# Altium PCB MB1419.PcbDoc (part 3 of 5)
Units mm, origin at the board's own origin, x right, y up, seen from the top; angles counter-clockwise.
Board outline 31 x 41 mm, 8 copper layers (Top Layer, Signal Layer 1, Signal Layer 2, Signal Layer 3, Signal Layer 4, Signal Layer 5, Signal Layer 6, Bottom Layer), stack 1.536 mm thick; 212 components, 125 nets, 637 pads, 2405 vias.
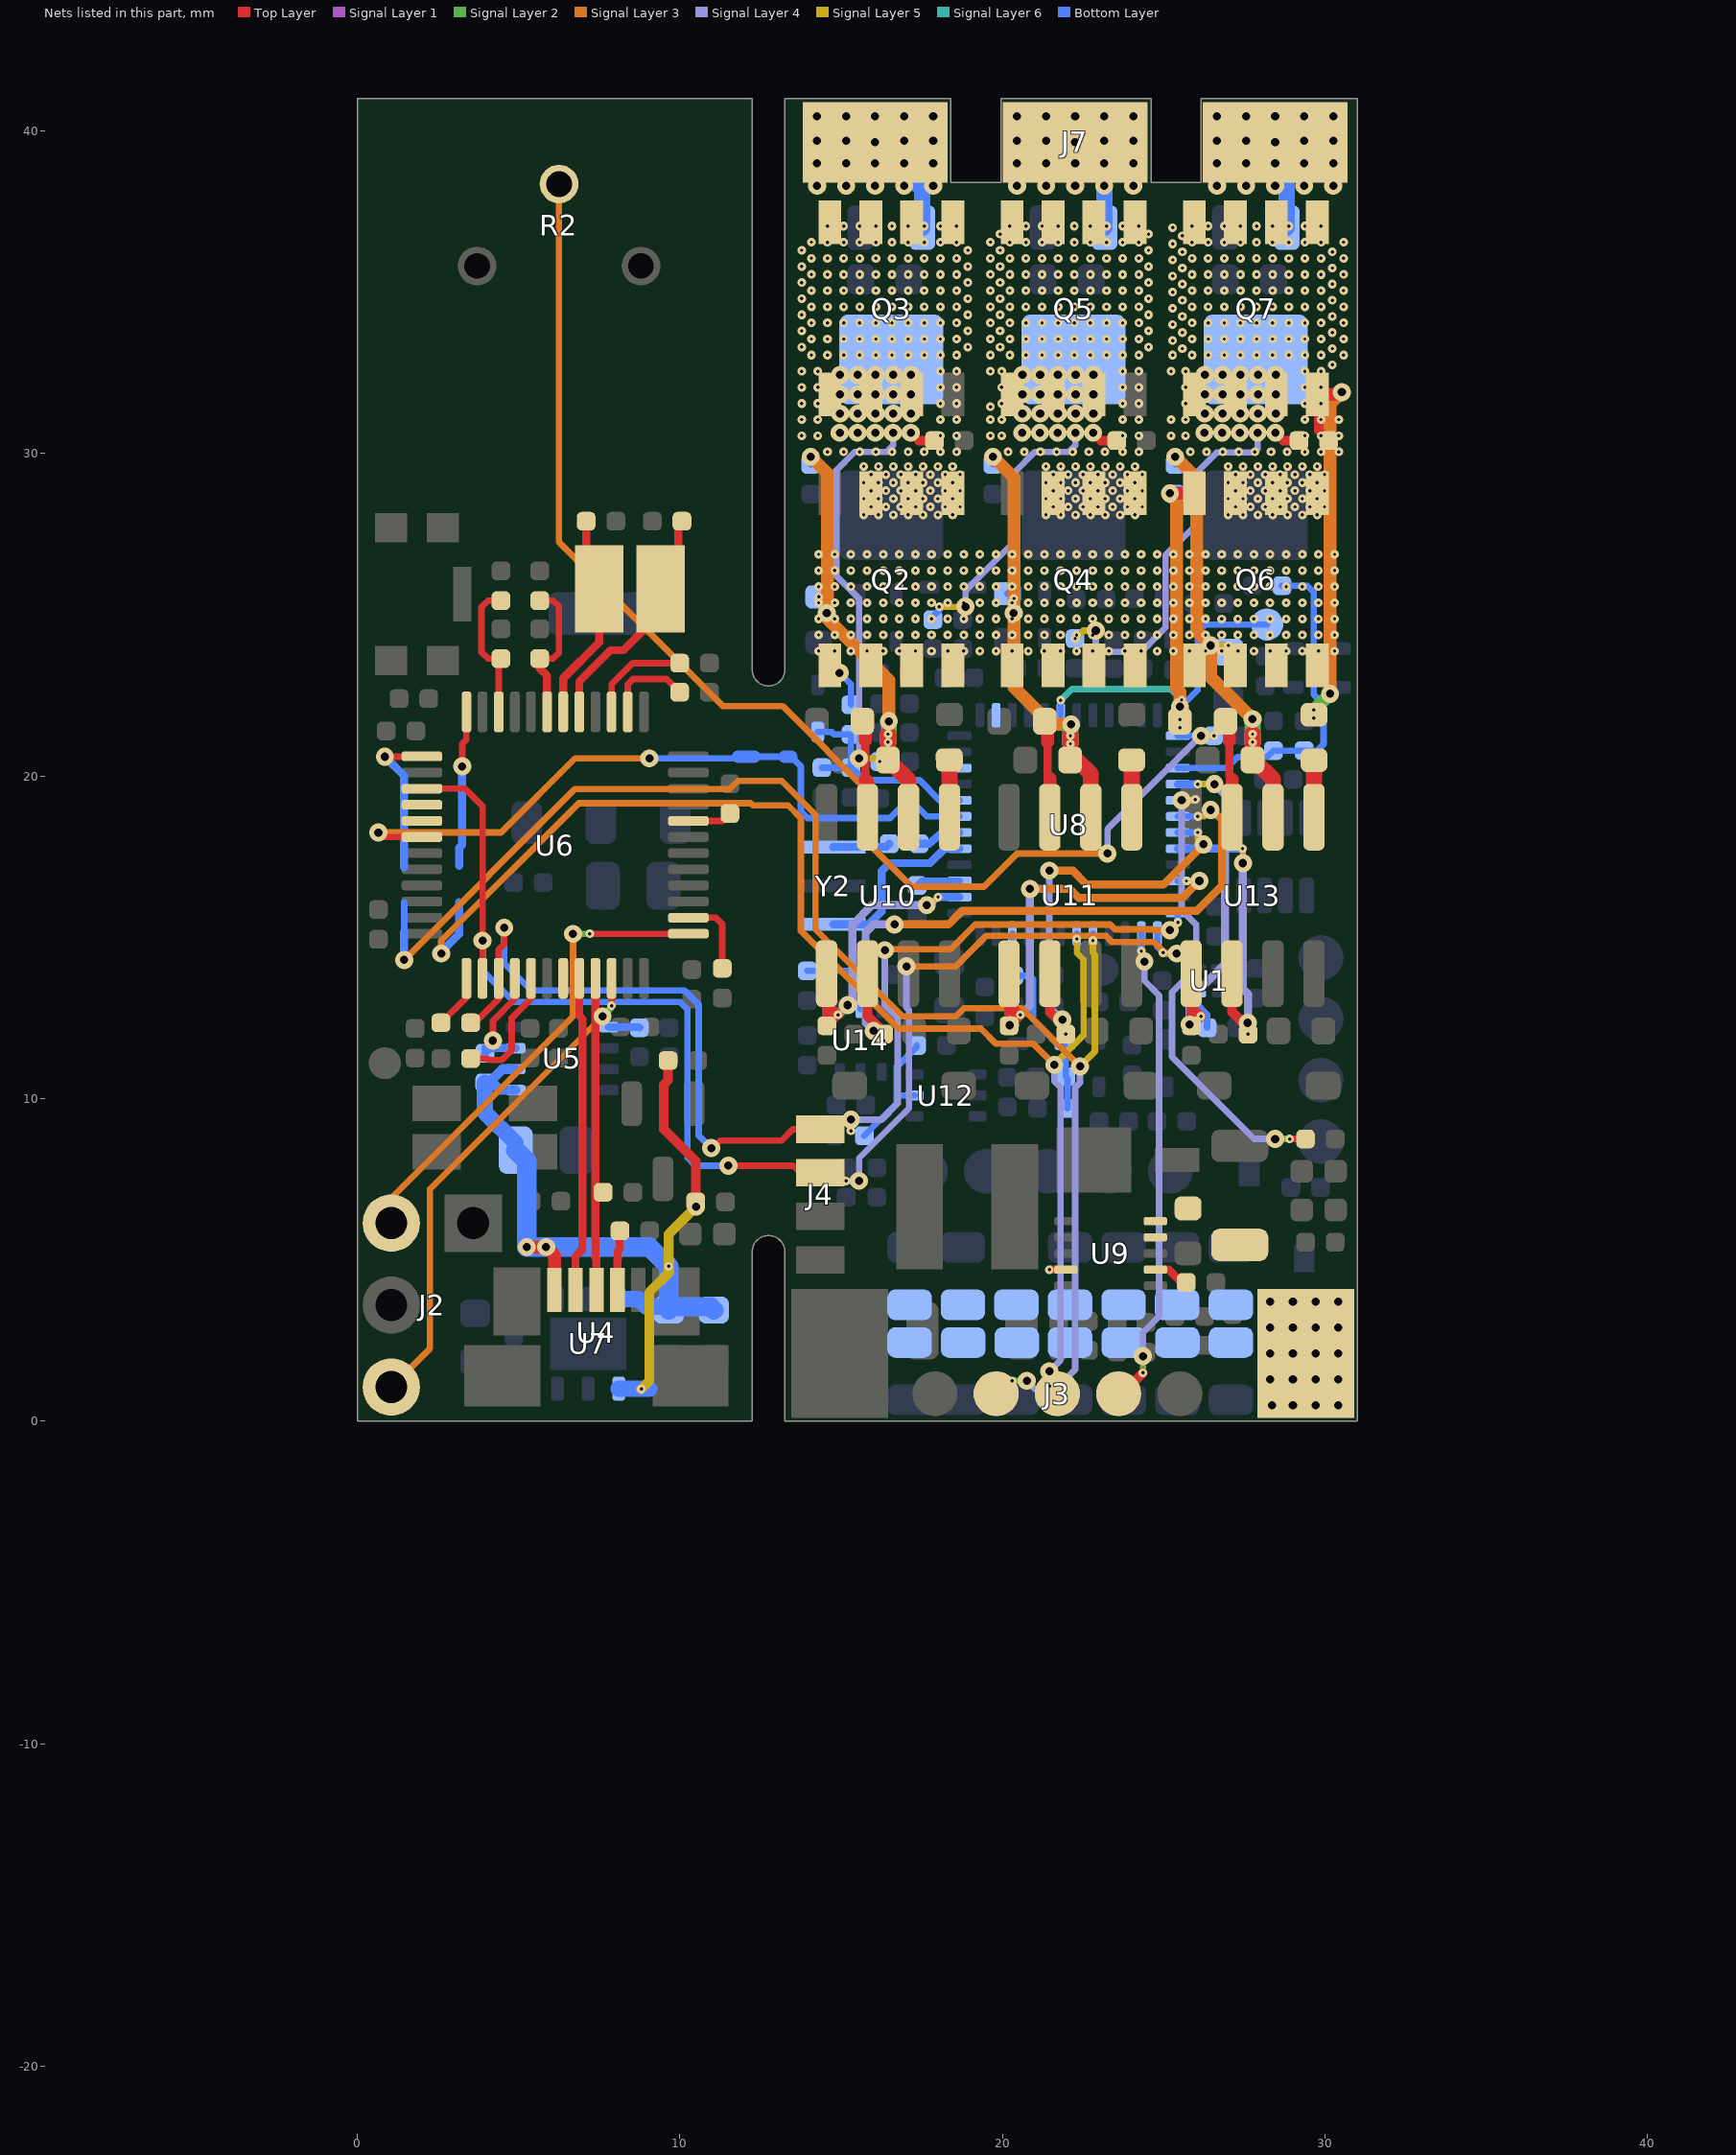
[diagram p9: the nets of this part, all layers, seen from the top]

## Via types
v1: diameter 0.27, hole 0.1, Top Layer to Signal Layer 1, 715 vias
v2: diameter 0.27, hole 0.1, Signal Layer 6 to Bottom Layer, 503 vias
v3: diameter 0.27, hole 0.1, Signal Layer 1 to Signal Layer 2, 497 vias
v4: diameter 0.27, hole 0.1, Signal Layer 5 to Signal Layer 6, 309 vias
v5: diameter 0.559, hole 0.254, Top Layer to Bottom Layer, 214 vias
v6: diameter 0.559, hole 0.254, Signal Layer 2 to Signal Layer 5, 155 vias
v7: diameter 0.254, hole 0.254, Top Layer to Bottom Layer, 12 vias

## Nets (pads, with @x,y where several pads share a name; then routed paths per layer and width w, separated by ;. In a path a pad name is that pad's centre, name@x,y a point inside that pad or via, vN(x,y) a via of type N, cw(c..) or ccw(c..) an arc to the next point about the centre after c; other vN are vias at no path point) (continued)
NetQ6_4: Q6.4 R47.2 R48.1 | length 8.6
  Top Layer w0.2: v3(25.5,21.5) R47.2@25.5,21.7 R47.2@25.545,21.7
  Top Layer w0.4: v5(25.184,28.765) Q6.4@25.945,28.765
  Signal Layer 2 w0.4: v3(25.5,21.5) v3(25.5,21.75) v6(25.5,22.15)
  Signal Layer 3 w0.4: v5(25.184,28.765) 25.4,28.549 25.4,22.7 25.5,22.6 v6(25.5,22.15)
  Bottom Layer w0.2: v5(25.184,28.765) 25.325,28.765 R48.1@25.35,28.74
  other v1: 25.5,21.5 25.5,21.75
NetQ7_4: Q7.4 R50.2 R52.1 | length 13.1
  Top Layer w0.2: v3(29.65,21.8) 29.655,21.805 R50.2@29.655,21.9 R50.2@29.65,21.905 ; R52.1@30,30.51 30,30.5 30.1,30.4 R52.1@30.11,30.4
  Top Layer w0.3: Q7.4@29.755,31.835 29.8,31.79 29.8,30.71 30,30.51 R52.1@30.11,30.4
  Top Layer w0.4: Q7.4@29.755,31.835 30.385,31.835 30.45,31.9 v5(30.516,31.9)
  Signal Layer 2 w0.4: v3(29.65,21.8) v3(29.65,22.05) v6(30.15,22.55)
  Signal Layer 3 w0.4: v6@30.15,22.5 v6(30.15,22.55) 30.15,31.534 v5(30.516,31.9)
  other v1: 29.65,21.8 29.65,22.05
NetR7_2: R7.2 U4.4 | length 1.9
  Top Layer w0.25: U4.4@8.06,4.074 8.06,5.011 8.07,5.021 8.07,5.288 8.14,5.358 R7.2@8.14,5.9
NetR13_1: R13.1 U6.44 | length 1.4
  Top Layer w0.2: U6.44@10.26,18.61 11.32,18.61 R13.1@11.55,18.84
NetR14_1: R14.1 U5.5 | length 1
  Bottom Layer w0.25: U5.5@7.795,12.215 8.725,12.215 R14.1@8.74,12.2
NetR16_1: R16.1 U6.2 | length 2.7
  Top Layer w0.2: U6.2@8.38,21.99 8.38,22.847 8.54,23.007 9.583,23.007 R16.1@9.99,22.6
NetR17_1: R17.1 U6.3 | length 3.2
  Top Layer w0.2: U6.3@7.88,21.99 7.88,22.847 8.533,23.5 R17.1@9.99,23.5
NetR18_2: R18.2 U6.29 | length 3.9
  Top Layer w0.2: R18.2@3.51,11.24 4.027,11.24 4.067,11.2 4.48,11.2 4.78,11.5 4.78,12.498 5.38,13.098 U6.29@5.38,13.73
NetR19_1: R19.1 R22.1 U6.10 | length 4.4
  Top Layer w0.2: U6.10@4.38,21.99 4.38,23.57 R22.1@4.45,23.64 4.048,23.64 3.848,23.84 3.848,25.24 4.048,25.44 R19.1@4.45,25.44
NetR23_2: R23.2 U6.12 | length 4.9
  Top Layer w0.2: v5(3.25,20.3) 3.25,21.003 3.38,21.133 U6.12@3.38,21.99
  Bottom Layer w0.25: R23.2@3.15,17.22 3.15,17.767 3.25,17.867 v5(3.25,20.3)
NetR24_2: R24.2 U6.13 | length 4.8
  Top Layer w0.2: v5(0.85,20.6) 1.99,20.6 U6.13@2,20.61
  Bottom Layer w0.25: v5(0.85,20.6) 1.45,20 R24.2@1.45,17.22 1.45,17.17
NetR26_1: R26.1 U8.3 | length 1.4
  Bottom Layer w0.2: R26.1@17.35,16.61 17.49,16.75 U8.3@18.665,16.75
NetR27_1: R27.1 Y2.3 | length 1.8
  Bottom Layer w0.25: Y2.3@14.75,17.8 16.196,17.805 16.395,17.805 R27.1@16.49,17.9
NetR27_2: R27.2 U8.6 | length 1.4
  Bottom Layer w0.25: R27.2@17.41,17.9 17.721,17.9 18.121,18.25 U8.6@18.665,18.25
NetR32_1: R32.1 U9.7 | length 1.1
  Top Layer w0.25: U9.7@24.735,4.7 25.149,4.7 25.549,4.3 R32.1@25.69,4.3
NetR34_1: R34.1 U10.7 | length 3.1
  Top Layer w0.2: R34.1@15.655,21.7 R34.1@15.695,21.7
  Top Layer w0.25: 15.75,19.9 15.75,21.1
  Top Layer w0.4: R34.1@15.655,21.7 15.75,21.605 15.75,21.1 ; 15.75,19.9 15.815,19.835 U10.7@15.815,18.725
NetR38_1: R38.1 U10.5 | length 1.8
  Top Layer w0.5: R38.1@18.35,20.495 18.355,20.49 U10.5@18.355,18.725
NetR40_1: R40.1 U11.7 | length 3
  Top Layer w0.25: 21.4,21.05 21.4,19.984 21.465,19.919
  Top Layer w0.4: R40.1@21.305,21.7 21.4,21.605 21.4,21.05 ; U11.7@21.465,18.725 21.465,19.919
NetR42_1: R42.1 R46.1 U12.2 | length 4
  Bottom Layer w0.2: R42.1@15.71,8.85 16.715,9.855 16.715,10.1 ; U12.2@17.275,10.1 16.715,10.1 ; R46.1@17.34,11.65 17.34,11.604 16.715,10.979 16.715,10.1
NetR43_1: R43.1 U11.5 | length 1.8
  Top Layer w0.5: R43.1@24,20.495 24.005,20.49 U11.5@24.005,18.725
NetR47_1: R47.1 U13.7 | length 3.1
  Top Layer w0.25: 27.03,21.081 27.03,19.985 27.115,19.9
  Top Layer w0.4: R47.1@26.91,21.7 26.955,21.7 27.03,21.625 27.03,21.081 ; U13.7@27.115,18.725 27.115,19.9
NetR49_1: R49.1 R53.1 U14.2 | length 3
  Bottom Layer w0.2: R49.1@13.95,13.96 15.63,13.96 R53.1@15.74,13.85 15.632,13.742 15.632,13.314 15.6,13.282 U14.2@15.6,12.775
NetR50_1: R50.1 U13.5 | length 1.8
  Top Layer w0.5: U13.5@29.655,18.725 R50.1@29.655,20.49
NetU8_5: U8.5 Y2.1 | length 5.6
  Bottom Layer w0.25: Y2.1@14.75,15.4 15.85,15.4 16.25,15.8 16.25,17.05 16.5,17.3 17.75,17.3 18.2,17.75 U8.5@18.665,17.75
OP1_OUT: U8.10 | length 0.9
  Bottom Layer w0.2: 18.005,20.65 18.005,20.54 18.295,20.25 U8.10@18.665,20.25
OP2_OUT: U8.14
OP3_OUT: TP3.1 U8.18 | length 9.2
  Signal Layer 6 w0.2: v2(21.8,22.35) 22.15,22.7 25.21,22.7 v2(25.55,22.36)
  Bottom Layer w0.2: U8.18@21.8,21.885 v2(21.8,22.35) ; v2(25.55,22.36) 25.56,22.37 25.75,22.37 26.05,22.67 26.05,24.45 26.3,24.7 TP3.1@28.2,24.7
OSC_IN: C11.2 U6.5 Y1.1 | length 7.5
  Top Layer w0.25: U6.5@6.88,21.99 6.88,22.93 7.85,23.9 8.25,23.9 8.8,24.45 8.8,25.3 9.3,25.8 Y1.1@9.4,25.8 9.4,25.9 9.95,26.45 9.95,27.79 C11.2@10.06,27.9
OSC_OUT: C10.2 U6.6 Y1.2 | length 6.6
  Top Layer w0.25: U6.6@6.38,21.99 6.38,23.03 7.5,24.15 Y1.2@7.5,25.8 7.34,25.8 7.09,26.05 C10.2@7.09,27.9
OUT1: C43.2 J7.3 Q2.1 Q2.2 Q2.3 Q3.5 Q3.6 Q3.7 Q3.8 R35.2 R37.1 R61.1 U10.6 | length 20.5
  Top Layer w0.5: C43.2@16.445,20.5 C43.2@16.45,20.5 ; v3(16.45,21.3) v3(16.45,21.05) C43.2@16.45,20.5 ; U10.6@17.085,18.025 U10.6@17.085,18.725 17.085,19.865 C43.2@16.45,20.5
  Signal Layer 1 w0.2: v5(14.25,39.7) 14.75,39.7 14.75,39.694 14.706,39.65 ; 14.85,39.65 J7.3@16.05,39.65
  Signal Layer 2 w0.5: v3(16.45,21.05) v3(16.45,21.3) 16.474,21.324 v6(16.474,21.7)
  Signal Layer 3 w0.2: v6(14.55,25.05) 14.55,24.9 v6@14.571,24.879 ; 14.55,25.5 14.571,25.521 14.65,25.6 14.65,26.221 14.571,26.3
  Signal Layer 3 w0.4: v5(14.05,29.9) 14.571,29.379 14.571,26.3 14.571,25.521 14.571,24.879 16.474,22.976 v6(16.474,21.7)
  Signal Layer 5 w0.2: v4(14.3,25.555) 14.445,25.41 14.445,25.155 v6(14.55,25.05)
  Bottom Layer w0.2: R35.2@14.05,29.66 v5(14.05,29.9) ; v4(14.3,25.555) 14.355,25.5 14.445,25.5 R61.1@14.45,25.495
  Bottom Layer w0.5: J7.3@16.05,39.65 16.825,38.875 17.175,38.525 17.51,38.19 R37.1@17.51,37
  other v1: 16.45,21.05 16.45,21.3 15.692,28.097 16.153,28.097 16.612,28.097 17.073,28.097 17.532,28.097 17.992,28.097 18.453,28.097 15.923,28.347 16.382,28.347 16.842,28.347 17.303,28.347 17.762,28.347 18.222,28.347 18.683,28.347 15.692,28.597 16.153,28.597 16.612,28.597 17.073,28.597 17.532,28.597 17.992,28.597 18.453,28.597 15.923,28.847 16.382,28.847 16.842,28.847 17.303,28.847 17.762,28.847 18.222,28.847 18.683,28.847 15.692,29.097 16.153,29.097 16.612,29.097 17.073,29.097 17.532,29.097 17.992,29.097 18.453,29.097 15.923,29.347 16.382,29.347 16.842,29.347 17.303,29.347 17.762,29.347 18.222,29.347 18.683,29.347 15.692,29.597 16.153,29.597 16.612,29.597 17.073,29.597 17.532,29.597 17.992,29.597 18.453,29.597 14.573,33.55 15.073,33.55 15.573,33.55 16.073,33.55 16.573,33.55 17.073,33.55 17.573,33.55 18.073,33.55 18.573,33.55 14.573,34.05 15.073,34.05 15.573,34.05 16.073,34.05 16.573,34.05 17.073,34.05 17.573,34.05 18.073,34.05 18.573,34.05 14.573,34.55 15.073,34.55 15.573,34.55 16.073,34.55 16.573,34.55 17.073,34.55 17.573,34.55 18.073,34.55 18.573,34.55 14.573,35.05 15.073,35.05 15.573,35.05 16.073,35.05 16.573,35.05 17.073,35.05 17.573,35.05 18.073,35.05 18.573,35.05 14.573,35.55 15.073,35.55 15.573,35.55 16.073,35.55 16.573,35.55 17.073,35.55 17.573,35.55 18.073,35.55 18.573,35.55 14.573,36.05 15.073,36.05 15.573,36.05 16.073,36.05 16.573,36.05 17.073,36.05 17.573,36.05 18.073,36.05 18.573,36.05 14.573,36.55 15.073,36.55 15.573,36.55 16.073,36.55 16.573,36.55 17.073,36.55 17.573,36.55 18.073,36.55 18.573,36.55 14.573,37.05 15.073,37.05 15.573,37.05 16.073,37.05 16.573,37.05 17.073,37.05 17.573,37.05 18.073,37.05 18.573,37.05
  other v2: 14.3,25.555
  other v3: 14.573,30.05 15.073,30.05 15.573,30.05 16.073,30.05 16.573,30.05 17.073,30.05 17.573,30.05 18.073,30.05 18.573,30.05 13.773,30.55 14.273,30.55 18.073,30.55 18.573,30.55 13.773,31.05 14.273,31.05 18.073,31.05 18.573,31.05 13.773,31.55 14.273,31.55 18.073,31.55 18.573,31.55 13.773,32.05 14.273,32.05 18.073,32.05 18.573,32.05 13.773,32.55 14.273,32.55 18.073,32.55 18.573,32.55 14.073,33.05 14.573,33.05 15.073,33.05 15.573,33.05 16.073,33.05 16.573,33.05 17.073,33.05 17.573,33.05 18.073,33.05 18.573,33.05 13.773,33.3 18.923,33.3 14.073,33.55 14.573,33.55 15.073,33.55 15.573,33.55 16.073,33.55 16.573,33.55 17.073,33.55 17.573,33.55 18.073,33.55 18.573,33.55 13.773,33.8 18.923,33.8 14.073,34.05 14.573,34.05 15.073,34.05 15.573,34.05 16.073,34.05 16.573,34.05 17.073,34.05 17.573,34.05 18.073,34.05 18.573,34.05 13.773,34.3 18.923,34.3 14.073,34.55 14.573,34.55 15.073,34.55 15.573,34.55 16.073,34.55 16.573,34.55 17.073,34.55 17.573,34.55 18.073,34.55 18.573,34.55 13.773,34.8 18.923,34.8 14.073,35.05 14.573,35.05 15.073,35.05 15.573,35.05 16.073,35.05 16.573,35.05 17.073,35.05 17.573,35.05 18.073,35.05 18.573,35.05 13.773,35.3 18.923,35.3 14.073,35.55 14.573,35.55 15.073,35.55 15.573,35.55 16.073,35.55 16.573,35.55 17.073,35.55 17.573,35.55 18.073,35.55 18.573,35.55 13.773,35.8 18.923,35.8 14.073,36.05 14.573,36.05 15.073,36.05 15.573,36.05 16.073,36.05 16.573,36.05 17.073,36.05 17.573,36.05 18.073,36.05 18.573,36.05 13.773,36.3 18.923,36.3 14.073,36.55 14.573,36.55 15.073,36.55 15.573,36.55 16.073,36.55 16.573,36.55 17.073,36.55 17.573,36.55 18.073,36.55 18.573,36.55 14.573,37.05 15.073,37.05 15.573,37.05 16.073,37.05 16.573,37.05 17.073,37.05 17.573,37.05 18.073,37.05 18.573,37.05
  other v5: 14.25,38.3 15.15,38.3 16.05,38.3 16.95,38.3 17.85,38.3 14.25,39 15.15,39 16.05,39 16.95,39 17.85,39 15.15,39.7 16.95,39.7 17.85,39.7 14.25,40.45 15.15,40.45 16.05,40.45 16.95,40.45 17.85,40.45
OUT2: C52.2 J7.2 Q4.1 Q4.2 Q4.3 Q5.5 Q5.6 Q5.7 Q5.8 R41.2 R44.1 R62.1 U11.6 | length 18.1
  Top Layer w0.5: C52.2@22.095,20.5 C52.2@22.1,20.5 ; v3(22.1,21.25) v3(22.1,21) C52.2@22.1,20.5 ; U11.6@22.735,18.725 22.735,20.065 22.3,20.5 C52.2@22.1,20.5
  Signal Layer 2 w0.5: v3(22.1,21) 22.1,21.3 22.1,21.576 v6(22.124,21.6)
  Signal Layer 3 w0.2: v6(20.345,25.055) 20.345,25.995 20.35,26
  Signal Layer 3 w0.4: v5(19.7,29.9) 20.35,29.25 20.35,26 20.35,22.75 21.5,21.6 v6(22.124,21.6)
  Signal Layer 5 w0.2: v6(20.345,25.055) 20.345,25.5 v4(20.35,25.505)
  Bottom Layer w0.2: R41.2@19.7,29.66 v5(19.7,29.9) ; R62.1@20.15,25.655 20.2,25.655 v4(20.35,25.505)
  Bottom Layer w0.5: J7.2@22.25,39.65 23.025,38.875 23.16,38.74 R44.1@23.16,37
  other v1: 22.1,21 22.1,21.25 21.342,28.097 21.802,28.097 22.263,28.097 22.722,28.097 23.182,28.097 23.643,28.097 24.102,28.097 21.572,28.347 22.032,28.347 22.493,28.347 22.952,28.347 23.413,28.347 23.872,28.347 24.332,28.347 21.342,28.597 21.802,28.597 22.263,28.597 22.722,28.597 23.182,28.597 23.643,28.597 24.102,28.597 21.572,28.847 22.032,28.847 22.493,28.847 22.952,28.847 23.413,28.847 23.872,28.847 24.332,28.847 21.342,29.097 21.802,29.097 22.263,29.097 22.722,29.097 23.182,29.097 23.643,29.097 24.102,29.097 21.572,29.347 22.032,29.347 22.493,29.347 22.952,29.347 23.413,29.347 23.872,29.347 24.332,29.347 21.342,29.597 21.802,29.597 22.263,29.597 22.722,29.597 23.182,29.597 23.643,29.597 24.102,29.597 20.223,33.55 20.723,33.55 21.223,33.55 21.723,33.55 22.223,33.55 22.723,33.55 23.223,33.55 23.723,33.55 24.223,33.55 20.223,34.05 20.723,34.05 21.223,34.05 21.723,34.05 22.223,34.05 22.723,34.05 23.223,34.05 23.723,34.05 24.223,34.05 20.223,34.55 20.723,34.55 21.223,34.55 21.723,34.55 22.223,34.55 22.723,34.55 23.223,34.55 23.723,34.55 24.223,34.55 20.223,35.05 20.723,35.05 21.223,35.05 21.723,35.05 22.223,35.05 22.723,35.05 23.223,35.05 23.723,35.05 24.223,35.05 20.223,35.55 20.723,35.55 21.223,35.55 21.723,35.55 22.223,35.55 22.723,35.55 23.223,35.55 23.723,35.55 24.223,35.55 19.923,35.8 24.523,35.8 19.623,36.05 20.223,36.05 20.723,36.05 21.223,36.05 21.723,36.05 22.223,36.05 22.723,36.05 23.223,36.05 23.723,36.05 24.223,36.05 19.923,36.3 24.523,36.3 19.623,36.55 20.223,36.55 20.723,36.55 21.223,36.55 21.723,36.55 22.223,36.55 22.723,36.55 23.223,36.55 23.723,36.55 24.223,36.55 19.923,36.8 24.523,36.8 20.223,37.05 20.723,37.05 21.223,37.05 21.723,37.05 22.223,37.05 22.723,37.05 23.223,37.05 23.723,37.05 24.223,37.05
  other v2: 20.35,25.505
  other v3: 20.173,30.05 20.673,30.05 21.173,30.05 21.673,30.05 22.173,30.05 22.673,30.05 23.173,30.05 23.723,30.05 24.223,30.05 19.623,30.55 19.973,30.55 23.723,30.55 24.223,30.55 19.623,31.05 19.973,31.05 23.723,31.05 24.223,31.05 19.623,31.45 19.973,31.55 23.723,31.55 24.223,31.55 19.973,32.05 23.723,32.05 24.223,32.05 19.623,32.55 19.973,32.55 23.723,32.55 24.223,32.55 19.623,33.05 20.223,33.05 20.723,33.05 21.223,33.05 21.723,33.05 22.223,33.05 22.723,33.05 23.223,33.05 23.723,33.05 24.223,33.05 19.923,33.3 24.523,33.3 19.623,33.55 20.223,33.55 20.723,33.55 21.223,33.55 21.723,33.55 22.223,33.55 22.723,33.55 23.223,33.55 23.723,33.55 24.223,33.55 19.923,33.8 24.523,33.8 19.623,34.05 20.223,34.05 20.723,34.05 21.223,34.05 21.723,34.05 22.223,34.05 22.723,34.05 23.223,34.05 23.723,34.05 24.223,34.05 19.923,34.3 24.523,34.3 19.623,34.55 20.223,34.55 20.723,34.55 21.223,34.55 21.723,34.55 22.223,34.55 22.723,34.55 23.223,34.55 23.723,34.55 24.223,34.55 19.923,34.8 24.523,34.8 19.623,35.05 20.223,35.05 20.723,35.05 21.223,35.05 21.723,35.05 22.223,35.05 22.723,35.05 23.223,35.05 23.723,35.05 24.223,35.05 19.923,35.3 24.523,35.3 19.623,35.55 20.223,35.55 20.723,35.55 21.223,35.55 21.723,35.55 22.223,35.55 22.723,35.55 23.223,35.55 23.723,35.55 24.223,35.55 19.923,35.8 24.523,35.8 19.623,36.05 20.223,36.05 20.723,36.05 21.223,36.05 21.723,36.05 22.223,36.05 22.723,36.05 23.223,36.05 23.723,36.05 24.223,36.05 19.923,36.3 24.523,36.3 19.623,36.55 20.223,36.55 20.723,36.55 21.223,36.55 21.723,36.55 22.223,36.55 22.723,36.55 23.223,36.55 23.723,36.55 24.223,36.55 19.923,36.8 24.523,36.8 20.223,37.05 20.723,37.05 21.223,37.05 21.723,37.05 22.223,37.05 22.723,37.05 23.223,37.05 23.723,37.05 24.223,37.05
  other v5: 20.45,38.3 21.35,38.3 22.25,38.3 23.15,38.3 24.05,38.3 20.45,39 21.35,39 22.25,39 23.15,39 24.05,39 20.45,39.7 21.35,39.7 23.15,39.7 24.05,39.7 20.45,40.45 21.35,40.45 22.25,40.45 23.15,40.45 24.05,40.45
OUT3: C58.2 J7.1 Q6.1 Q6.2 Q6.3 Q7.5 Q7.6 Q7.7 Q7.8 R48.2 R51.1 R63.1 U13.6 | length 16.5
  Top Layer w0.5: C58.2@27.745,20.5 C58.2@27.75,20.5 ; v3(27.75,21.3) v3(27.75,21.05) C58.2@27.75,20.5 ; U13.6@28.385,18.725 28.385,19.9 27.785,20.5 C58.2@27.75,20.5
  Signal Layer 2 w0.5: v3(27.75,21.05) v3(27.75,21.3) v6(27.75,21.766)
  Signal Layer 3 w0.4: v5(25.35,29.9) 26.021,29.229 26.021,24.479 v6(26.45,24.05) 26.45,23.066 v6(27.75,21.766)
  Signal Layer 5 w0.2: v6(26.45,24.05) v4(27,24.05)
  Bottom Layer w0.2: R48.2@25.35,29.66 v5(25.35,29.9) ; R63.1@27,23.845 v4(27,24.05) ; v5(28.45,39) J7.1@28.45,39.65
  Bottom Layer w0.5: v5(28.45,39) 28.45,38.906 28.753,38.603 28.81,38.546 R51.1@28.81,37
  other v1: 27.75,21.05 27.75,21.3 26.992,28.097 27.453,28.097 27.912,28.097 28.372,28.097 28.833,28.097 29.292,28.097 29.753,28.097 27.223,28.347 27.682,28.347 28.142,28.347 28.603,28.347 29.062,28.347 29.522,28.347 29.983,28.347 26.992,28.597 27.453,28.597 27.912,28.597 28.372,28.597 28.833,28.597 29.292,28.597 29.753,28.597 27.223,28.847 27.682,28.847 28.142,28.847 28.603,28.847 29.062,28.847 29.522,28.847 29.983,28.847 26.992,29.097 27.453,29.097 27.912,29.097 28.372,29.097 28.833,29.097 29.292,29.097 29.753,29.097 27.223,29.347 27.682,29.347 28.142,29.347 28.603,29.347 29.062,29.347 29.522,29.347 29.983,29.347 26.992,29.597 27.453,29.597 27.912,29.597 28.372,29.597 28.833,29.597 29.292,29.597 29.753,29.597 25.873,33.55 26.373,33.55 26.873,33.55 27.373,33.55 27.873,33.55 28.373,33.55 28.873,33.55 29.373,33.55 29.873,33.55 25.873,34.05 26.373,34.05 26.873,34.05 27.373,34.05 27.873,34.05 28.373,34.05 28.873,34.05 29.373,34.05 29.873,34.05 25.873,34.55 26.373,34.55 26.873,34.55 27.373,34.55 27.873,34.55 28.373,34.55 28.873,34.55 29.373,34.55 29.873,34.55 25.873,35.05 26.373,35.05 26.873,35.05 27.373,35.05 27.873,35.05 28.373,35.05 28.873,35.05 29.373,35.05 29.873,35.05 25.873,35.55 26.373,35.55 26.873,35.55 27.373,35.55 27.873,35.55 28.373,35.55 28.873,35.55 29.373,35.55 29.873,35.55 25.573,35.75 30.223,35.75 25.273,36 25.873,36.05 26.373,36.05 26.873,36.05 27.373,36.05 27.873,36.05 28.373,36.05 28.873,36.05 29.373,36.05 29.873,36.05 25.573,36.25 30.223,36.25 25.273,36.5 25.873,36.55 26.373,36.55 26.873,36.55 27.373,36.55 27.873,36.55 28.373,36.55 28.873,36.55 29.373,36.55 29.873,36.55 25.573,36.75 25.273,37 25.873,37.05 26.373,37.05 26.873,37.05 27.373,37.05 27.873,37.05 28.373,37.05 28.873,37.05 29.373,37.05 29.873,37.05
  other v2: 27,24.05
  other v3: 25.823,30.05 26.323,30.05 26.823,30.05 27.323,30.05 27.823,30.05 28.323,30.05 28.823,30.05 29.373,30.05 29.873,30.05 30.423,30.05 25.223,30.55 25.673,30.55 29.373,30.55 29.873,30.55 30.423,30.55 25.223,31.05 25.673,31.05 29.373,31.05 29.873,31.05 30.423,31.05 25.673,31.55 29.373,31.55 29.873,31.55 25.673,32.05 29.373,32.05 29.873,32.05 25.223,32.55 25.673,32.55 29.373,32.55 29.873,32.55 30.223,32.75 25.273,33.05 25.873,33.05 26.373,33.05 26.873,33.05 27.373,33.05 27.873,33.05 28.373,33.05 28.873,33.05 29.373,33.05 29.873,33.05 30.573,33.05 25.573,33.25 30.223,33.25 25.273,33.5 25.873,33.55 26.373,33.55 26.873,33.55 27.373,33.55 27.873,33.55 28.373,33.55 28.873,33.55 29.373,33.55 29.873,33.55 30.573,33.55 25.573,33.75 30.223,33.75 25.273,34 25.873,34.05 26.373,34.05 26.873,34.05 27.373,34.05 27.873,34.05 28.373,34.05 28.873,34.05 29.373,34.05 29.873,34.05 30.573,34.05 25.573,34.25 30.223,34.25 25.273,34.5 25.873,34.55 26.373,34.55 26.873,34.55 27.373,34.55 27.873,34.55 28.373,34.55 28.873,34.55 29.373,34.55 29.873,34.55 30.573,34.55 25.573,34.75 30.223,34.75 25.273,35 25.873,35.05 26.373,35.05 26.873,35.05 27.373,35.05 27.873,35.05 28.373,35.05 28.873,35.05 29.373,35.05 29.873,35.05 30.573,35.05 25.573,35.25 30.223,35.25 25.273,35.5 25.873,35.55 26.373,35.55 26.873,35.55 27.373,35.55 27.873,35.55 28.373,35.55 28.873,35.55 29.373,35.55 29.873,35.55 30.573,35.55 25.573,35.75 30.223,35.75 25.273,36 25.873,36.05 26.373,36.05 26.873,36.05 27.373,36.05 27.873,36.05 28.373,36.05 28.873,36.05 29.373,36.05 29.873,36.05 30.573,36.05 25.573,36.25 30.223,36.25 25.273,36.5 25.873,36.55 26.373,36.55 26.873,36.55 27.373,36.55 27.873,36.55 28.373,36.55 28.873,36.55 29.373,36.55 29.873,36.55 30.573,36.55 25.573,36.75 25.273,37 25.873,37.05 26.373,37.05 26.873,37.05 27.373,37.05 27.873,37.05 28.373,37.05 28.873,37.05 29.373,37.05 29.873,37.05
  other v5: 26.65,38.3 27.55,38.3 28.45,38.3 29.35,38.3 30.25,38.3 26.65,39 27.55,39 29.35,39 30.25,39 26.65,39.7 27.55,39.7 29.35,39.7 30.25,39.7 26.65,40.45 27.55,40.45 28.45,40.45 29.35,40.45 30.25,40.45
"PA0 - BUSV": C23.1 D16.A R68.2 R76.1 U8.8 | length 6.8
  Bottom Layer w0.2: D16.A@14.27,21.37 14.697,21.37 14.747,21.32 14.753,21.32 14.783,21.29 R68.2@15.3,21.29 R76.1@15.3,20.26 ; C23.1@14.4,20.26 R76.1@15.3,20.26 ; U8.8@18.665,19.25 18.048,19.25 17.428,19.87 15.757,19.87 R76.1@15.3,20.26
PC13-UL: C47.1 U8.2 U10.1 | length 10.2
  Top Layer w0.3: v3(14.9,12.6) 14.894,12.6 v1@14.892,12.602 ; U10.1@14.55,12.944 14.545,12.949 U10.1@14.545,13.875 14.55,13.87 U10.1@14.55,12.944 ; U10.1@14.55,12.944 v1@14.892,12.602 ; U10.1@14.55,12.944 C47.1@14.55,12.26 v1@14.892,12.602
  Signal Layer 2 w0.3: v3(14.9,12.6) v6(15.2,12.9)
  Signal Layer 4 w0.25: v6(15.2,12.9) 15.35,13.05 15.35,15.4 15.95,16 v6(17.65,16)
  Signal Layer 5 w0.2: v6(17.65,16) 17.75,16 v4(18,16.25)
  Bottom Layer w0.25: v4(18,16.25) U8.2@18.665,16.25
  other v1: 14.9,12.6
  other v2: 18,16.25
PWM: J3.4 U8.38 | length 15
  Top Layer w0.2: J3.4@23.6,0.85 J3.4@23.7,0.85
  Top Layer w0.3: J3.4@23.7,0.85 v3(24.35,1.5)
  Signal Layer 2 w0.2: v3(24.35,1.5) v6(24.35,2.016)
  Signal Layer 4 w0.2: v6(24.35,2.016) 24.35,2.75 24.85,3.25 24.85,13.2 24.4,13.65 v6(24.4,14.25)
  Signal Layer 5 w0.2: v6@24.3,14.5 24.3,14.4 24.4,14.3 v6(24.4,14.25)
  Bottom Layer w0.2: v4(24.3,14.575) U8.38@24.3,15.115
  other v1: 24.35,1.5
  other v2: 24.3,14.575
PWR_ENN: R12.2 U5.3 U6.28 | length 4.1
  Top Layer w0.2: v5(4.2,11.8) 4.2,12.406 4.259,12.466 4.259,12.473 4.88,13.093 U6.28@4.88,13.73
  Bottom Layer w0.2: R12.2@3.95,11.41 R12.2@3.95,11.55 ; R12.2@3.95,11.55 v5(4.2,11.8) 4.15,11.8 3.95,11.6 R12.2@3.95,11.55
  Bottom Layer w0.25: R12.2@3.95,11.41 4.105,11.565 U5.3@4.905,11.565
S1: R1.1 U1.4 | length 1.2
  Bottom Layer w0.2: U1.4@25.98,13.25 25.98,12.97 26.34,12.61 R1.1@26.34,12.2
SPEED: C22.1 R2.2 U8.25 | length 40.3
  Signal Layer 3 w0.2: R2.2@6.25,38.355 6.25,27.25 11.327,22.173 13.177,22.173 15.95,19.4 15.95,17.8 17.179,16.571 19.421,16.571 20.45,17.6 v6(23.25,17.6)
  Signal Layer 4 w0.2: v6(23.25,17.6) 23.25,18.35 v6(26.15,21.25)
  Signal Layer 5 w0.2: v6(26.15,21.25) v4(26.55,21.25)
  Bottom Layer w0.2: U8.25@25.435,21.25 C22.1@26.54,21.25 v4(26.55,21.25)
  other v2: 26.55,21.25
STATUS: R28.1 U8.29 | length 14.7
  Top Layer w0.2: v3(28.9,8.75) R28.1@29.39,8.75
  Signal Layer 2 w0.2: v6(28.45,8.75) v3(28.9,8.75)
  Signal Layer 4 w0.2: v6(25.55,19.25) 25.55,15.849 26,15.399 26,14.05 25.25,13.3 25.25,11.3 27.8,8.75 v6(28.45,8.75)
  Signal Layer 5 w0.2: v6(25.55,19.25) 25.95,19.25 v4(25.975,19.275)
  Bottom Layer w0.2: U8.29@25.435,19.25 25.993,19.25 v2@26.025,19.282
  other v1: 28.9,8.75
  other v2: 25.975,19.275
STM_JTCK: J2.2 U6.37 | length 14.9
  Top Layer w0.2: v3(7.2,15.11) U6.37@10.26,15.11
  Signal Layer 2 w0.2: v6(6.684,15.11) v3(7.2,15.11)
  Signal Layer 3 w0.2: J2.2@1.05,6.14 1.05,6.916 6.684,12.55 v6(6.684,15.11)
  other v1: 7.2,15.11
STM_JTMS: J2.4 U6.34 | length 15.5
  Top Layer w0.2: v3(7.88,12.88) U6.34@7.88,13.73
  Signal Layer 2 w0.2: v6(7.6,12.55) 7.88,12.83 v3(7.88,12.88)
  Signal Layer 3 w0.2: J2.4@1.05,1.06 2.25,2.26 2.25,7.2 v6(7.6,12.55)
  other v1: 7.88,12.88
STM_RST: C13.1 R15.2 U6.7 | length 4.5
  Top Layer w0.2: C13.1@5.65,23.64 6.06,23.64 6.25,23.83 6.25,25.25 6.06,25.44 R15.2@5.65,25.44
  Top Layer w0.25: C13.1@5.65,23.64 5.65,23.34 5.88,23.11 U6.7@5.88,21.99
T_JTCK: J4.2 U6.15 U6.26 U8.37 | length 42.9
  Top Layer w0.2: U6.15@2,19.61 3.34,19.61 3.88,19.07 v5(3.88,14.9) U6.26@3.88,13.73 ; v5(11.5,7.923) 13.511,7.923 13.534,7.9 13.792,7.642 13.85,7.7 J4.2@14.35,7.7 14.85,7.7 14.862,7.688 14.912,7.688 v3(15.15,7.45)
  Signal Layer 2 w0.2: v3(15.15,7.45) v6(15.55,7.45)
  Signal Layer 3 w0.2: v6(17.021,14.1) 18.55,14.1 19.5,15.05 23.194,15.05 23.386,14.858 24.692,14.858 25.05,14.5 v6(25.4,14.5)
  Signal Layer 4 w0.2: v6(15.55,7.45) 15.55,8.15 17.1,9.7 17.1,12.75 17.021,12.829 v6(17.021,14.1)
  Signal Layer 5 w0.2: v4@24.975,14.506 25.394,14.506 v6(25.4,14.5)
  Bottom Layer w0.2: v5(3.88,14.9) 3.88,13.97 4.85,13 10,13 10.23,12.77 10.23,8.17 10.477,7.923 v5(11.5,7.923) ; U8.37@24.8,15.115 24.8,14.7 v4(24.975,14.525)
  other v1: 15.15,7.45
  other v2: 24.975,14.525
T_JTDI: U6.17
T_JTDO: U6.16
T_JTMS: J4.1 R20.2 U6.27 U8.36 | length 36.6
  Top Layer w0.2: R20.2@3.51,12.35 3.642,12.35 4.38,13.088 U6.27@4.38,13.73 4.38,14.621 4.55,14.791 v5(4.55,15.3) ; v5(10.969,8.469) 11.019,8.469 11.25,8.7 13.15,8.7 13.5,9.05 J4.1@14.35,9.05 14.4,9.1 J4.1@14.85,9.1
  Signal Layer 2 w0.2: v6@15.3,9.1 v6(15.3,9.35)
  Signal Layer 3 w0.2: v6(16.35,14.6) 16.45,14.6 16.479,14.629 18.379,14.629 19.15,15.4 23.339,15.4 23.489,15.25 24.654,15.25 24.683,15.222 v6(25.189,15.222)
  Signal Layer 4 w0.2: v6(15.3,9.35) 16.255,9.35 16.75,9.845 16.75,12.5 16.35,12.9 v6(16.35,14.6)
  Signal Layer 5 w0.2: v6(25.189,15.222) 25.432,15.465 v4(25.435,15.465)
  Bottom Layer w0.2: v5(4.55,15.3) 4.55,14.2 5.4,13.35 10.145,13.35 10.58,12.915 10.58,8.858 v5(10.969,8.469) ; v4(25.435,15.465) U8.36@25.435,15.75
  other v1: 15.3,9
  other v2: 25.435,15.465
  other v3: 15.3,9
T_NRST: C21.1 U6.18 U8.7 | length 22.5
  Top Layer w0.2: v5(0.65,18.25) 0.79,18.11 U6.18@2,18.11
  Signal Layer 3 w0.2: v5(0.65,18.25) 4.45,18.25 6.75,20.55 v5(9.05,20.55)
  Bottom Layer w0.2: v5(9.05,20.55) 11.75,20.55 11.8,20.6 ; 12.3,20.6 13.25,20.6 ; 13.45,20.6 13.75,20.3 13.75,18.901 13.95,18.701 15.656,18.701 ; 15.657,18.7 16.51,18.7 C21.1@17.11,19.3 17.66,18.75 U8.7@18.665,18.75
  Bottom Layer w0.4: 11.8,20.6 12.3,20.6 ; 13.25,20.6 13.45,20.6
T_SWDIO_IN: R20.1 U6.25 | length 1.7
  Top Layer w0.2: R20.1@2.59,12.35 3.38,13.14 U6.25@3.38,13.73
T_SWO: U6.31
"TEMPERATURE FEEDBACK": C66.1 R60.1 RT1.2 U8.27 | length 10.7
  Bottom Layer w0.2: U8.27@25.435,20.25 26.95,20.25 27.296,20.596 28.205,20.596 C66.1@28.4,20.79 R60.1@29.35,20.79 29.75,20.79 29.95,20.99 29.95,22.223 29.65,22.523 29.65,25.7 29.45,25.9 RT1.2@28.66,25.9
U5V: C7.1 C14.1 C15.1 R3.2 R12.1 R21.1 U4.1 U5.1 U5.2 U7.1 U7.6 | length 31.5
  Top Layer w0.3: R3.2@9.63,11.18 9.63,10.563 9.5,10.433 9.5,9.05 10.49,8.06 R21.1@10.49,6.8
  Top Layer w0.4: v5(5.25,5.4) v5(5.85,5.4) 6.111,5.139 U4.1@6.111,4.074 ; R21.1@10.49,6.8 10.49,6.66 v5(10.5,6.65)
  Signal Layer 5 w0.3: v4(8.8,1) 9.05,1.25 9.05,4 9.65,4.6 v4(9.65,4.8) 9.65,5.8 v5(10.5,6.65)
  Bottom Layer w0.2: 8.5,1 8.508,1.008
  Bottom Layer w0.3: R12.1@3.95,10.49 R12.1@4.075,10.49 ; U5.1@4.905,10.265 4.425,10.265 4.2,10.49 R12.1@4.075,10.49 ; U5.2@4.905,10.915 4.5,10.915 R12.1@4.075,10.49
  Bottom Layer w0.5: R12.1@3.95,10.49 3.95,9.575 4.91,8.615 C7.1@4.91,8.4 ; U7.1@8.1,1.01 8.49,1.01 8.5,1 v4(8.8,1) ; U7.6@8.1,3.79 8.713,3.79 8.958,3.545 9.55,3.545 C14.1@9.65,3.445 ; 8.508,1.008 8.791,1.008 v4(8.8,1) ; 9.05,1 v4(8.8,1)
  Bottom Layer w0.6: C7.1@4.91,8.4 5.25,8.06 v5(5.25,5.4) v5(5.85,5.4) 9.05,5.4 v4(9.65,4.8) C14.1@9.65,3.445 9.75,3.545 10.95,3.545 C15.1@11.05,3.445
  other v2: 8.8,1 9.65,4.8
UH: C48.1 U8.30 U10.2 | length 21.1
  Top Layer w0.2: C48.1@16.278,12 16.278,11.932 C48.1@16.288,11.922 ; C48.1@16.288,11.978 C48.1@16.31,12
  Top Layer w0.3: U10.2@15.815,13.875 15.815,12.563 16.288,12.09 16.288,11.978 C48.1@16.288,11.922
  Signal Layer 2 w0.3: v6(16,12.1) 16.01,12.1 v3(16.31,11.8)
  Signal Layer 3 w0.25: v6(16.65,15.4) 18.325,15.4 18.75,15.825 26.025,15.825 26.811,16.611 26.811,18.66 v6(26.45,18.95)
  Signal Layer 4 w0.25: v6(16,12.1) 15.754,12.346 15.754,15.15 16.004,15.4 v6(16.65,15.4)
  Signal Layer 5 w0.2: v4(26.052,18.75) 26.25,18.75 v6(26.45,18.95)
  Bottom Layer w0.2: U8.30@25.435,18.75 v4(26.052,18.75)
  other v1: 16.31,11.8
  other v2: 26.052,18.75
USART2_RX: J3.3 R23.1 U8.42 | length 43.5
  Top Layer w0.2: v3(21.45,1.087) 21.513,1.087 21.7,0.9 J3.3@21.7,0.85
  Signal Layer 2 w0.2: v3(21.45,1.087) v6(21.45,1.55)
  Signal Layer 3 w0.2: v5(2.6,14.501) 2.6,14.9 6.859,19.159 12.191,19.159 12.257,19.093 13.353,19.093 13.75,18.696 13.75,15.205 16.784,12.171 19.329,12.171 19.8,11.7 20.951,11.7 v6(21.601,11.051)
  Signal Layer 4 w0.2: v6(21.45,1.55) 21.8,1.9 21.8,10.345 21.601,10.544 v6(21.601,11.051)
  Signal Layer 5 w0.2: v6(21.601,11.051) 22.509,11.959 22.509,14.319 22.3,14.528 v4(22.3,14.95)
  Bottom Layer w0.2: v4(22.3,14.95) U8.42@22.3,15.115
  Bottom Layer w0.25: v5(2.6,14.501) 2.6,14.55 3.15,15.1 R23.1@3.15,16.085
  other v1: 21.45,1.087
  other v2: 22.3,14.95
USART2_RX_ST_LINK: J3.2 R24.1 U8.41 | length 47.7
  Top Layer w0.2: J3.2@19.8,0.85 19.9,0.85 v3(20.3,1.25)
  Signal Layer 2 w0.2: v3(20.3,1.25) v6(20.75,1.25)
  Signal Layer 3 w0.2: v5(1.45,14.3) 6.75,19.6 11.549,19.6 11.799,19.85 13.15,19.85 14.2,18.8 14.2,15.25 16.9,12.55 18.55,12.55 18.804,12.804 20.596,12.804 v6(22.4,11)
  Signal Layer 4 w0.2: v6(20.75,1.25) 21,1 21.649,1 22.25,1.601 22.25,10.344 22.4,10.494 v6(22.4,11)
  Signal Layer 5 w0.2: v6(22.4,11) 22.859,11.459 22.859,14.464 22.8,14.523 v4(22.8,14.9)
  Bottom Layer w0.2: 1.45,15.16 R24.1@1.45,16.085 ; v4(22.8,14.9) U8.41@22.8,15.115
  Bottom Layer w0.25: v5(1.45,14.3) 1.45,15.16
  other v1: 20.3,1.25
  other v2: 22.8,14.9
USB_DM: U4.2 U6.32 | length 9.8
  Top Layer w0.25: U4.2@6.761,4.074 6.761,5.111 6.98,5.33 6.98,12.47 6.88,12.57 U6.32@6.88,13.73
USB_DP: R5.2 U4.3 U6.33 | length 9.9
  Top Layer w0.2: R5.2@7.38,7.1 R5.2@7.62,7.1
  Top Layer w0.25: U6.33@7.38,13.73 7.38,7.1 7.38,5.07 7.411,5.039 7.411,4.075 U4.3@7.41,4.074
USB_RENUMN: R4.1 U6.38 | length 2.5
  Top Layer w0.2: U6.38@10.26,15.61 11.117,15.61 11.31,15.417 R4.1@11.31,14.04
V+: C27.2 C28.2 C29.2 C30.2 C31.2 C32.2 C33.2 C34.2 C35.2 C36.2 C37.2 C38.2 C39.2 C40.2 C41.1 C44.1 D20.C J5.1 Q2.5 Q2.6 Q2.7 Q2.8 Q4.5 Q4.6 Q4.7 Q4.8 Q6.5 Q6.6 Q6.7 Q6.8 R68.1 U9.4 U9.9 U9.10 | length 1.7
  Top Layer w0.2: Q2.5@14.64,23.43 Q2.5@14.645,23.435
  Top Layer w0.25: v1(21.45,4.7) U9.4@21.965,4.7
  Bottom Layer w0.2: v5(14.95,23.2) 15.3,22.85 R68.1@15.3,22.21
  other v1: 14.298,23.875 14.798,23.875 15.298,23.875 15.798,23.875 16.298,23.875 16.798,23.875 17.298,23.875 17.798,23.875 18.298,23.875 18.796,23.874 19.296,23.874 19.796,23.874 20.296,23.874 20.796,23.874 21.296,23.874 21.796,23.874 22.296,23.874 22.794,23.874 23.294,23.874 23.794,23.874 24.294,23.874 24.794,23.874 25.294,23.874 25.794,23.874 26.294,23.874 26.792,23.873 27.292,23.873 27.792,23.873 28.292,23.873 28.792,23.873 29.292,23.873 29.792,23.873 30.292,23.873 14.298,24.375 14.798,24.375 15.298,24.375 15.798,24.375 16.298,24.375 16.798,24.375 17.298,24.375 17.798,24.375 18.298,24.375 18.796,24.374 19.296,24.374 19.796,24.374 20.296,24.374 20.796,24.374 21.296,24.374 21.796,24.374 22.296,24.374 22.794,24.374 23.294,24.374 23.794,24.374 24.294,24.374 24.794,24.374 25.294,24.374 25.794,24.374 26.294,24.374 26.792,24.373 27.292,24.373 27.792,24.373 28.292,24.373 28.792,24.373 29.292,24.373 29.792,24.373 30.292,24.373 14.298,24.875 14.798,24.875 15.298,24.875 15.798,24.875 16.298,24.875 16.798,24.875 17.298,24.875 17.798,24.875 18.298,24.875 18.796,24.874 19.296,24.874 19.796,24.874 20.296,24.874 20.796,24.874 21.296,24.874 21.796,24.874 22.296,24.874 22.794,24.874 23.294,24.874 23.794,24.874 24.294,24.874 24.794,24.874 25.294,24.874 25.794,24.874 26.294,24.874 26.792,24.873 27.292,24.873 27.792,24.873 28.292,24.873 28.792,24.873 29.292,24.873 29.792,24.873 30.292,24.873 14.298,25.375 14.798,25.375 15.298,25.375 15.798,25.375 16.298,25.375 16.798,25.375 17.298,25.375 17.798,25.375 18.298,25.375 18.796,25.374 19.296,25.374 19.796,25.374 20.296,25.374 20.796,25.374 21.296,25.374 21.796,25.374 22.296,25.374 22.794,25.374 23.294,25.374 23.794,25.374 24.294,25.374 24.794,25.374 25.294,25.374 25.794,25.374 26.294,25.374 26.792,25.373 27.292,25.373 27.792,25.373 28.292,25.373 28.792,25.373 29.292,25.373 29.792,25.373 30.292,25.373 14.298,25.875 14.798,25.875 15.298,25.875 15.798,25.875 16.298,25.875 16.798,25.875 17.298,25.875 17.798,25.875 18.298,25.875 18.796,25.874 19.296,25.874 19.796,25.874 20.296,25.874 20.796,25.874 21.296,25.874 21.796,25.874 22.296,25.874 22.794,25.874 23.294,25.874 23.794,25.874 24.294,25.874 24.794,25.874 25.294,25.874 25.794,25.874 26.294,25.874 26.792,25.873 27.292,25.873 27.792,25.873 28.292,25.873 28.792,25.873 29.292,25.873 29.792,25.873 30.292,25.873 14.298,26.375 14.798,26.375 15.298,26.375 15.798,26.375 16.298,26.375 16.798,26.375 17.298,26.375 17.798,26.375 18.298,26.375 18.796,26.374 19.296,26.374 19.796,26.374 20.296,26.374 20.796,26.374 21.296,26.374 21.796,26.374 22.296,26.374 22.794,26.374 23.294,26.374 23.794,26.374 24.294,26.374 24.794,26.374 25.294,26.374 25.794,26.374 26.294,26.374 26.792,26.373 27.292,26.373 27.792,26.373 28.292,26.373 28.792,26.373 29.292,26.373 29.792,26.373 30.292,26.373 14.298,26.875 14.798,26.875 15.298,26.875 15.798,26.875 16.298,26.875 16.798,26.875 17.298,26.875 17.798,26.875 18.298,26.875 18.796,26.874 19.296,26.874 19.796,26.874 20.296,26.874 20.796,26.874 21.296,26.874 21.796,26.874 22.296,26.874 22.794,26.874 23.294,26.874 23.794,26.874 24.294,26.874 24.794,26.874 25.294,26.874 25.794,26.874 26.294,26.874 26.792,26.873 27.292,26.873 27.792,26.873 28.292,26.873 28.792,26.873 29.292,26.873 29.792,26.873 30.292,26.873
  other v5: 28.35,0.5 29,0.5 29.7,0.5 30.4,0.5 28.3,1.3 29,1.3 29.7,1.3 30.4,1.3 28.3,2.1 29,2.1 29.7,2.1 30.4,2.1 28.3,2.9 29,2.9 29.7,2.9 30.4,2.9 28.3,3.7 29,3.7 29.7,3.7 30.4,3.7
VH: C54.1 U8.31 U11.2 | length 13.9
  Top Layer w0.3: U11.2@21.465,13.875 21.465,12.685 21.96,12.19 v3(21.96,12)
  Signal Layer 2 w0.3: v6(21.85,12.45) 21.96,12.34 v3(21.96,12)
  Signal Layer 3 w0.25: v6(21.45,17.071) 22.179,17.071 22.613,16.637 24.983,16.637 v6(26.229,17.884)
  Signal Layer 4 w0.2: v6(21.45,17.071) 21.45,12.85 v6(21.85,12.45)
  Signal Layer 5 w0.2: v4(26.05,18.25) 26.05,18.063 v6(26.229,17.884)
  Bottom Layer w0.2: U8.31@25.435,18.25 v4(26.05,18.25)
  other v1: 21.96,12
  other v2: 26.05,18.25
VL: C53.1 U8.34 U11.1 | length 14.7
  Top Layer w0.3: v3(20.55,12.6) v1@20.54,12.6 ; U11.1@20.2,12.94 20.195,12.945 U11.1@20.195,13.875 20.2,13.87 U11.1@20.2,12.94 ; U11.1@20.2,12.94 v1@20.54,12.6 ; U11.1@20.2,12.94 C53.1@20.2,12.26 v1@20.54,12.6
  Signal Layer 2 w0.3: v6(20.225,12.275) v3(20.55,12.6)
  Signal Layer 3 w0.25: v6(20.85,16.5) 22.079,16.5 22.354,16.225 25.575,16.225 v6(26.1,16.75)
  Signal Layer 4 w0.25: v6(20.225,12.275) 20.85,12.9 v6(20.85,16.5)
  Signal Layer 5 w0.2: v4(25.7,16.75) v6(26.1,16.75)
  Bottom Layer w0.2: U8.34@25.435,16.75 v4(25.7,16.75)
  other v1: 20.55,12.6
  other v2: 25.7,16.75
"VSHUNT_1 +": Q3.1 Q3.2 Q3.3 R39.2 R54.1 R67.2 | length 15.3
  Top Layer w0.2: v5@15.355,30.645 v5(15.505,30.645) ; v5@15.905,30.645 v5@16.015,30.645
  Top Layer w0.3: 17.409,30.4 R39.2@17.89,30.4
  Signal Layer 4 w0.2: v6(15.55,20.55) 15.55,25.505 14.85,26.205 14.85,29.48 15.42,30.05 16.405,30.05 16.605,30.25 v5(16.605,30.645)
  Signal Layer 5 w0.2: v6(15.55,20.55) 16.09,20.55 v4(16.19,20.45)
  Bottom Layer w0.2: v5@14.815,31.235 v5(14.965,31.235) v5@15.365,31.235 ; v5@15.905,30.645 v5(16.055,30.645) v5(16.605,30.645) v5@17.005,30.645 ; v5@15.915,31.235 v5(16.065,31.235) v5@16.465,31.235
  other v2: 16.19,20.45
  other v5: 14.955,30.645 17.155,30.645 15.515,31.235 16.615,31.235 17.165,31.235 14.965,31.835 15.515,31.835 16.065,31.835 16.615,31.835 17.165,31.835 14.965,32.435 15.515,32.435 16.065,32.435 16.615,32.435 17.165,32.435
"VSHUNT_2 +": Q5.1 Q5.2 Q5.3 R45.2 R55.1 R69.2 | length 9.3
  Top Layer w0.2: v5@21.055,30.645 v5(21.155,30.645)
  Top Layer w0.3: 23.059,30.4 R45.2@23.54,30.4
  Signal Layer 4 w0.2: v6(18.85,25.25) 18.85,25.75 20.4,27.3 20.4,29.445 21.005,30.05 22.055,30.05 22.255,30.25 v5(22.255,30.645)
  Signal Layer 5 w0.2: v4(18.04,25.25) v6(18.85,25.25)
  Bottom Layer w0.2: R69.2@17.84,24.85 17.84,24.95 18.04,25.15 v4(18.04,25.25)
  other v2: 18.04,25.25
  other v5: 20.605,30.645 21.705,30.645 22.805,30.645 20.615,31.235 21.165,31.235 21.715,31.235 22.265,31.235 22.815,31.235 20.615,31.835 21.165,31.835 21.715,31.835 22.265,31.835 22.815,31.835 20.615,32.435 21.165,32.435 21.715,32.435 22.265,32.435 22.815,32.435
"VSHUNT_3 +": Q7.1 Q7.2 Q7.3 R52.2 R56.1 R70.2 | length 12.2
  Top Layer w0.3: 28.709,30.4 R52.2@29.19,30.4
  Signal Layer 4 w0.2: v6(22.89,24.51) 22.89,24.004 23.044,23.85 24.305,23.85 25.05,24.595 25.05,26.845 25.95,27.745 25.95,29.345 26.635,30.03 27.8,30.03 27.905,30.135 v5(27.905,30.645)
  Signal Layer 5 w0.2: v4(22.25,24.26) 22.5,24.51 v6(22.89,24.51)
  other v2: 22.25,24.26
  other v5: 26.255,30.645 26.805,30.645 27.355,30.645 28.455,30.645 26.265,31.235 26.815,31.235 27.365,31.235 27.915,31.235 28.465,31.235 26.265,31.835 26.815,31.835 27.365,31.835 27.915,31.835 28.465,31.835 26.265,32.435 26.815,32.435 27.365,32.435 27.915,32.435 28.465,32.435
WH: C61.1 U8.32 U13.2 | length 9.9
  Top Layer w0.3: U13.2@27.115,13.875 27.115,12.685 27.61,12.19 v3(27.61,12)
  Signal Layer 2 w0.3: v6(27.6,12.35) 27.61,12.34 v3(27.61,12)
  Signal Layer 4 w0.2: v6(27.6,12.35) 27.6,12.45 27.61,12.46 v6@27.61,12.5
  Signal Layer 4 w0.25: v6(27.45,17.3) 27.45,13.4 27.61,13.24 v6@27.61,12.5
  Signal Layer 5 w0.2: v4@27.437,17.74 27.45,17.727 v6(27.45,17.3)
  Bottom Layer w0.25: U8.32@25.435,17.75 v4(27.437,17.75)
  other v1: 27.61,12
  other v2: 27.437,17.75
WL: C60.1 U8.28 U13.1 | length 13.2
  Top Layer w0.3: v3(26.15,12.55) v1@26.14,12.55 ; U13.1@25.85,12.84 C60.1@25.85,12.26 v1@26.14,12.55 ; U13.1@25.85,12.84 25.85,13.87 U13.1@25.845,13.875 25.845,12.845 U13.1@25.85,12.84 ; U13.1@25.85,12.84 v1@26.14,12.55
  Signal Layer 2 w0.3: v6(25.8,12.3) 26.05,12.55 v3(26.15,12.55)
  Signal Layer 4 w0.25: v6(25.8,12.3) 25.8,13.081 26.896,14.177 26.896,18.13 27.05,18.284 27.05,19.268 v6(26.568,19.75)
  Signal Layer 5 w0.2: v4(26.052,19.75) v6(26.568,19.75)
  Bottom Layer w0.25: U8.28@25.435,19.75 v4(26.052,19.75)
  other v1: 26.15,12.55
  other v2: 26.052,19.75
Z+/H3: C69.1 D19.A R73.1 R77.1 U8.46 | length 6.5
  Bottom Layer w0.2: U8.46@20.3,15.115 20.3,14.377 20.35,14.327 C69.1@20.35,13.81 20.84,13.81 20.95,13.7 20.95,12.45 21.7,11.7 D19.A@21.93,11.7 21.93,11.273 21.96,11.243 R73.1@21.96,10.68 22.01,10.63 R77.1@22.01,9.7
pads on no net: "SW1. " CART-8L-1.1 U1.6 U5.8 U6.4 U6.11 U6.14 U6.19 U6.21 U6.22 U6.40 U6.41 U6.42 U6.43 U6.45 U6.46 U7.3 U7.5 U8.4 U8.22 U8.26 U9.3 U12.3 U14.3
copper on no net: | length 3.1
  Top Layer w0.4: 0.55,8.9 ccw(c0.45,8.9) 0.55,8.9 ; 0.75,39.85 ccw(c0.65,39.85) 0.75,39.85 ; 30.65,13.4 ccw(c30.55,13.4) 30.65,13.4
  Bottom Layer w0.4: 1.1,39.7 ccw(c1,39.7) 1.1,39.7 ; 30.6,6.4 ccw(c30.5,6.4) 30.6,6.4
  other v7: 12.75,5.98 12.75,6.75 12.75,7.523 12.75,8.3 12.75,9.1 12.75,9.87 12.75,18.7 12.75,19.47 12.75,20.24 12.75,21.01 12.75,21.78 12.75,22.55

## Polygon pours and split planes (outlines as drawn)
no net on Top Solder (solid): 13.375,4.6 15.525,4.6 15.525,5.4 13.375,5.4 13.375,4.6
no net on Top Solder (solid): 13.4,5.95 15.55,5.95 15.55,6.75 13.4,6.75 13.4,5.95
no net on Top Solder (solid): 13.4,7.3 15.55,7.3 15.55,8.1 13.4,8.1 13.4,7.3
no net on Top Solder (solid): 13.4,8.65 15.55,8.65 15.55,9.45 13.4,9.45 13.4,8.65
no net on Top Solder (solid): 11.2,8.6 12.35,8.6 12.35,9.55 11.2,9.55 11.2,8.6
no net on Top Solder (solid): 11.25,7.9 11.25,7.3 12.3,7.3 12.3,8.15 11.5,8.15 11.45,8.1 11.25,7.9
no net on Top Solder (solid): 42 vertices, not listed, extent 24.8,0.075 26.2,1.575
no net on Top Solder (solid): 42 vertices, not listed, extent 22.9,0.075 24.3,1.575
no net on Top Solder (solid): 42 vertices, not listed, extent 21,0.075 22.4,1.575
no net on Top Solder (solid): 42 vertices, not listed, extent 19.1,0.075 20.5,1.575
no net on Top Solder (solid): 42 vertices, not listed, extent 17.2,0.1 18.6,1.6
no net on Bottom Solder "BOTTOM_N16851489_P497" (solid): 82 vertices, not listed, extent 22.6,7.05 24,8.45
no net on Bottom Solder "BOTTOM_N16851515_P495" (solid): 82 vertices, not listed, extent 20.7,7.05 22.1,8.45
no net on Bottom Solder "BOTTOM_N168514550_P492" (solid): 64 vertices, not listed, extent 24.5,7.05 25.9,8.45
no net on Bottom Solder "BOTTOM_GND_P496" (solid): 82 vertices, not listed, extent 16.9,7.05 18.3,8.45
no net on Bottom Solder "BOTTOM_5V_ESC_P494" (solid): 82 vertices, not listed, extent 18.8,7.05 20.2,8.45
no net on Bottom Solder "BOTTOM_OP1_OUT_P480" (solid): 18.05,20.75 18.05,21.95 17.95,22.05 17.7,22.05 17.65,22 17.65,20.75
no net on Bottom Solder (solid): 13.45,4.1 13.45,0.1 16.15,0.1 16.15,4.1 13.45,4.1
no net on Bottom Solder (solid): 11.3,6.9 12.3,6.9 12.3,7.45 11.3,7.45 11.3,6.9
no net on Bottom Solder (solid): 11.55,6.7 11.55,5.85 12.3,5.85 12.3,6.7 11.55,6.7
no net on Bottom Solder (solid): 13.15,6.65 13.15,6 14.2,6 14.2,6.65 13.15,6.65
no net on Bottom Solder (solid): 13.3,7.7 14.05,7.7 14.2,7.85 14.2,8.75 14,8.95 13.3,8.95 13.2,8.85 13.2,7.8 13.3,7.7
no net on Bottom Solder (solid): 11.5,9.05 12.25,9.05 12.35,8.95 12.35,8.5 12.25,8.4 11.55,8.4 11.45,8.5 11.45,9 11.5,9.05
no net on Bottom Solder (solid): 11.9,9.25 12.25,9.25 12.35,9.35 12.35,9.9 11.95,10.3 11.55,10.3 11.5,10.25 11.5,9.65 11.9,9.25
no net on Bottom Solder (solid): 13.25,9.3 14.15,9.3 14.2,9.35 14.2,10.45 14.15,10.5 13.8,10.5 13.25,9.95 13.25,9.3
no net on Bottom Solder (solid): 42 vertices, not listed, extent 29.25,13.7 30.725,15.05
no net on Bottom Solder (solid): 42 vertices, not listed, extent 29.25,11.8 30.725,13.15
no net on Bottom Solder (solid): 42 vertices, not listed, extent 29.25,9.9 30.725,11.25
no net on Bottom Solder (solid): 42 vertices, not listed, extent 29.225,7.95 30.725,9.35
+5V on Bottom Layer "+5V_L08_P000" (solid, pour order 0): 218 vertices, not listed, extent 0.25,14.8 11.95,40.7
GND on Bottom Layer "GND_L08_P002" (solid, pour order 2): 1962 vertices, not listed, extent 0.25,0.2 12.05,19.4
OP1_OUT on Bottom Layer "OP1_OUT_L08_P004" (solid, pour order 4): 18.2,20.45 18.05,20.6 18.05,21.95 17.95,22.05 17.7,22.05 17.65,22 17.65,20.75 17.95,20.45 18.2,20.45
+3.3V on Bottom Layer "+3.3V_L08_P006" (solid, pour order 6): 15.05,12.5 15.05,13 14.75,13.3 13.75,13.3 13.65,13.2 13.65,11.8 13.75,11.7 14.15,11.7 14.25,11.8 14.25,12.3 14.45,12.5 15.05,12.5
+3.3V on Bottom Layer "+3.3V_L08_P008" (solid, pour order 8): 17.95,15.2 17.95,13.9 18.25,13.6 18.75,13.6 19.15,13.2 19.65,13.2 19.65,13.7 19.45,13.7 19.35,13.8 19.35,14.7 19.05,14.7 18.75,15 18.75,15.3 18.05,15.3 17.95,15.2
5V_ESC on Bottom Layer "5V_ESC_L08_P010" (solid, pour order 10): 82 vertices, not listed, extent 18.8,7.05 20.2,8.45
5V_ESC on Bottom Layer "5V_ESC_L08_P012" (solid, pour order 12): 16.6,8.65 16.6,7.8 16.25,7.45 14.55,7.45 14.55,9.9 15.05,9.9 15.05,8.4 15.15,8.3 16.1,8.3 16.25,8.45 16.25,8.65 16.6,8.65
5V_ESC on Bottom Layer "5V_ESC_L08_P014" (solid, pour order 14): 13.15,7.45 13.15,6.95 14.25,6.95 14.25,7.45 13.15,7.45
5V_ESC on Bottom Layer "5V_ESC_L08_P016" (solid, pour order 16): 11.15,7.45 11.15,6.9 12.3,6.9 12.3,7.45 11.15,7.45
GND on Bottom Layer "GND_L08_P018" (solid, pour order 18): 334 vertices, not listed, extent 8.75,13.81 12.05,19.4
GND on Bottom Layer "GND_L08_P020" (solid, pour order 20): 272 vertices, not listed, extent 4.8,13.6 8.34,19.4
GND on Bottom Layer "GND_L08_P022" (solid, pour order 22): 98 vertices, not listed, extent 9.14,7.75 10.152,10.999
GND on Bottom Layer "GND_L08_P024" (solid, pour order 24): 42 vertices, not listed, extent 29.25,13.7 30.725,15.05
GND on Bottom Layer "GND_L08_P026" (solid, pour order 26): 28 vertices, not listed, extent 11.75,0.1 30.15,6.7
GND on Bottom Layer "GND_L08_P028" (solid, pour order 28): 82 vertices, not listed, extent 16.9,7.05 18.3,8.45
GND on Bottom Layer "GND_L08_P030" (solid, pour order 30): 26.2,29.5 26.2,28 24.9,28 24.9,26.5 30.6,26.5 30.6,29.5 26.2,29.5
GND on Bottom Layer "GND_L08_P032" (solid, pour order 32): 20.6,29.5 20.6,28 19.3,28 19.3,26.5 25,26.5 25,28 24.5,28 24.5,29.5 20.6,29.5
GND on Bottom Layer "GND_L08_P034" (solid, pour order 34): 14.95,29.5 14.95,28 13.65,28 13.65,26.5 19.35,26.5 19.35,28 18.85,28 18.85,29.5 14.95,29.5
NetJ8_1 on Bottom Layer "NETJ8_1_L08_P036" (solid, pour order 36): 64 vertices, not listed, extent 24.5,7.05 25.9,8.45
NetJ8_3 on Bottom Layer "NETJ8_3_L08_P038" (solid, pour order 38): 82 vertices, not listed, extent 20.7,7.05 22.1,8.45
NetJ8_2 on Bottom Layer "NETJ8_2_L08_P040" (solid, pour order 40): 82 vertices, not listed, extent 22.6,7.05 24,8.45
T_NRST on Bottom Layer "T_NRST_L08_P042" (solid, pour order 42): 11.3,20.975 11.3,19.925 12.3,19.925 12.3,20.975 11.3,20.975
T_NRST on Bottom Layer "T_NRST_L08_P044" (solid, pour order 44): 13.15,21 13.15,19.95 13.9,19.95 13.9,21 13.15,21
NetJ1_3 on Bottom Layer "NETJ1_3_L08_P046" (solid, pour order 46): 42 vertices, not listed, extent 29.25,11.8 30.725,13.15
